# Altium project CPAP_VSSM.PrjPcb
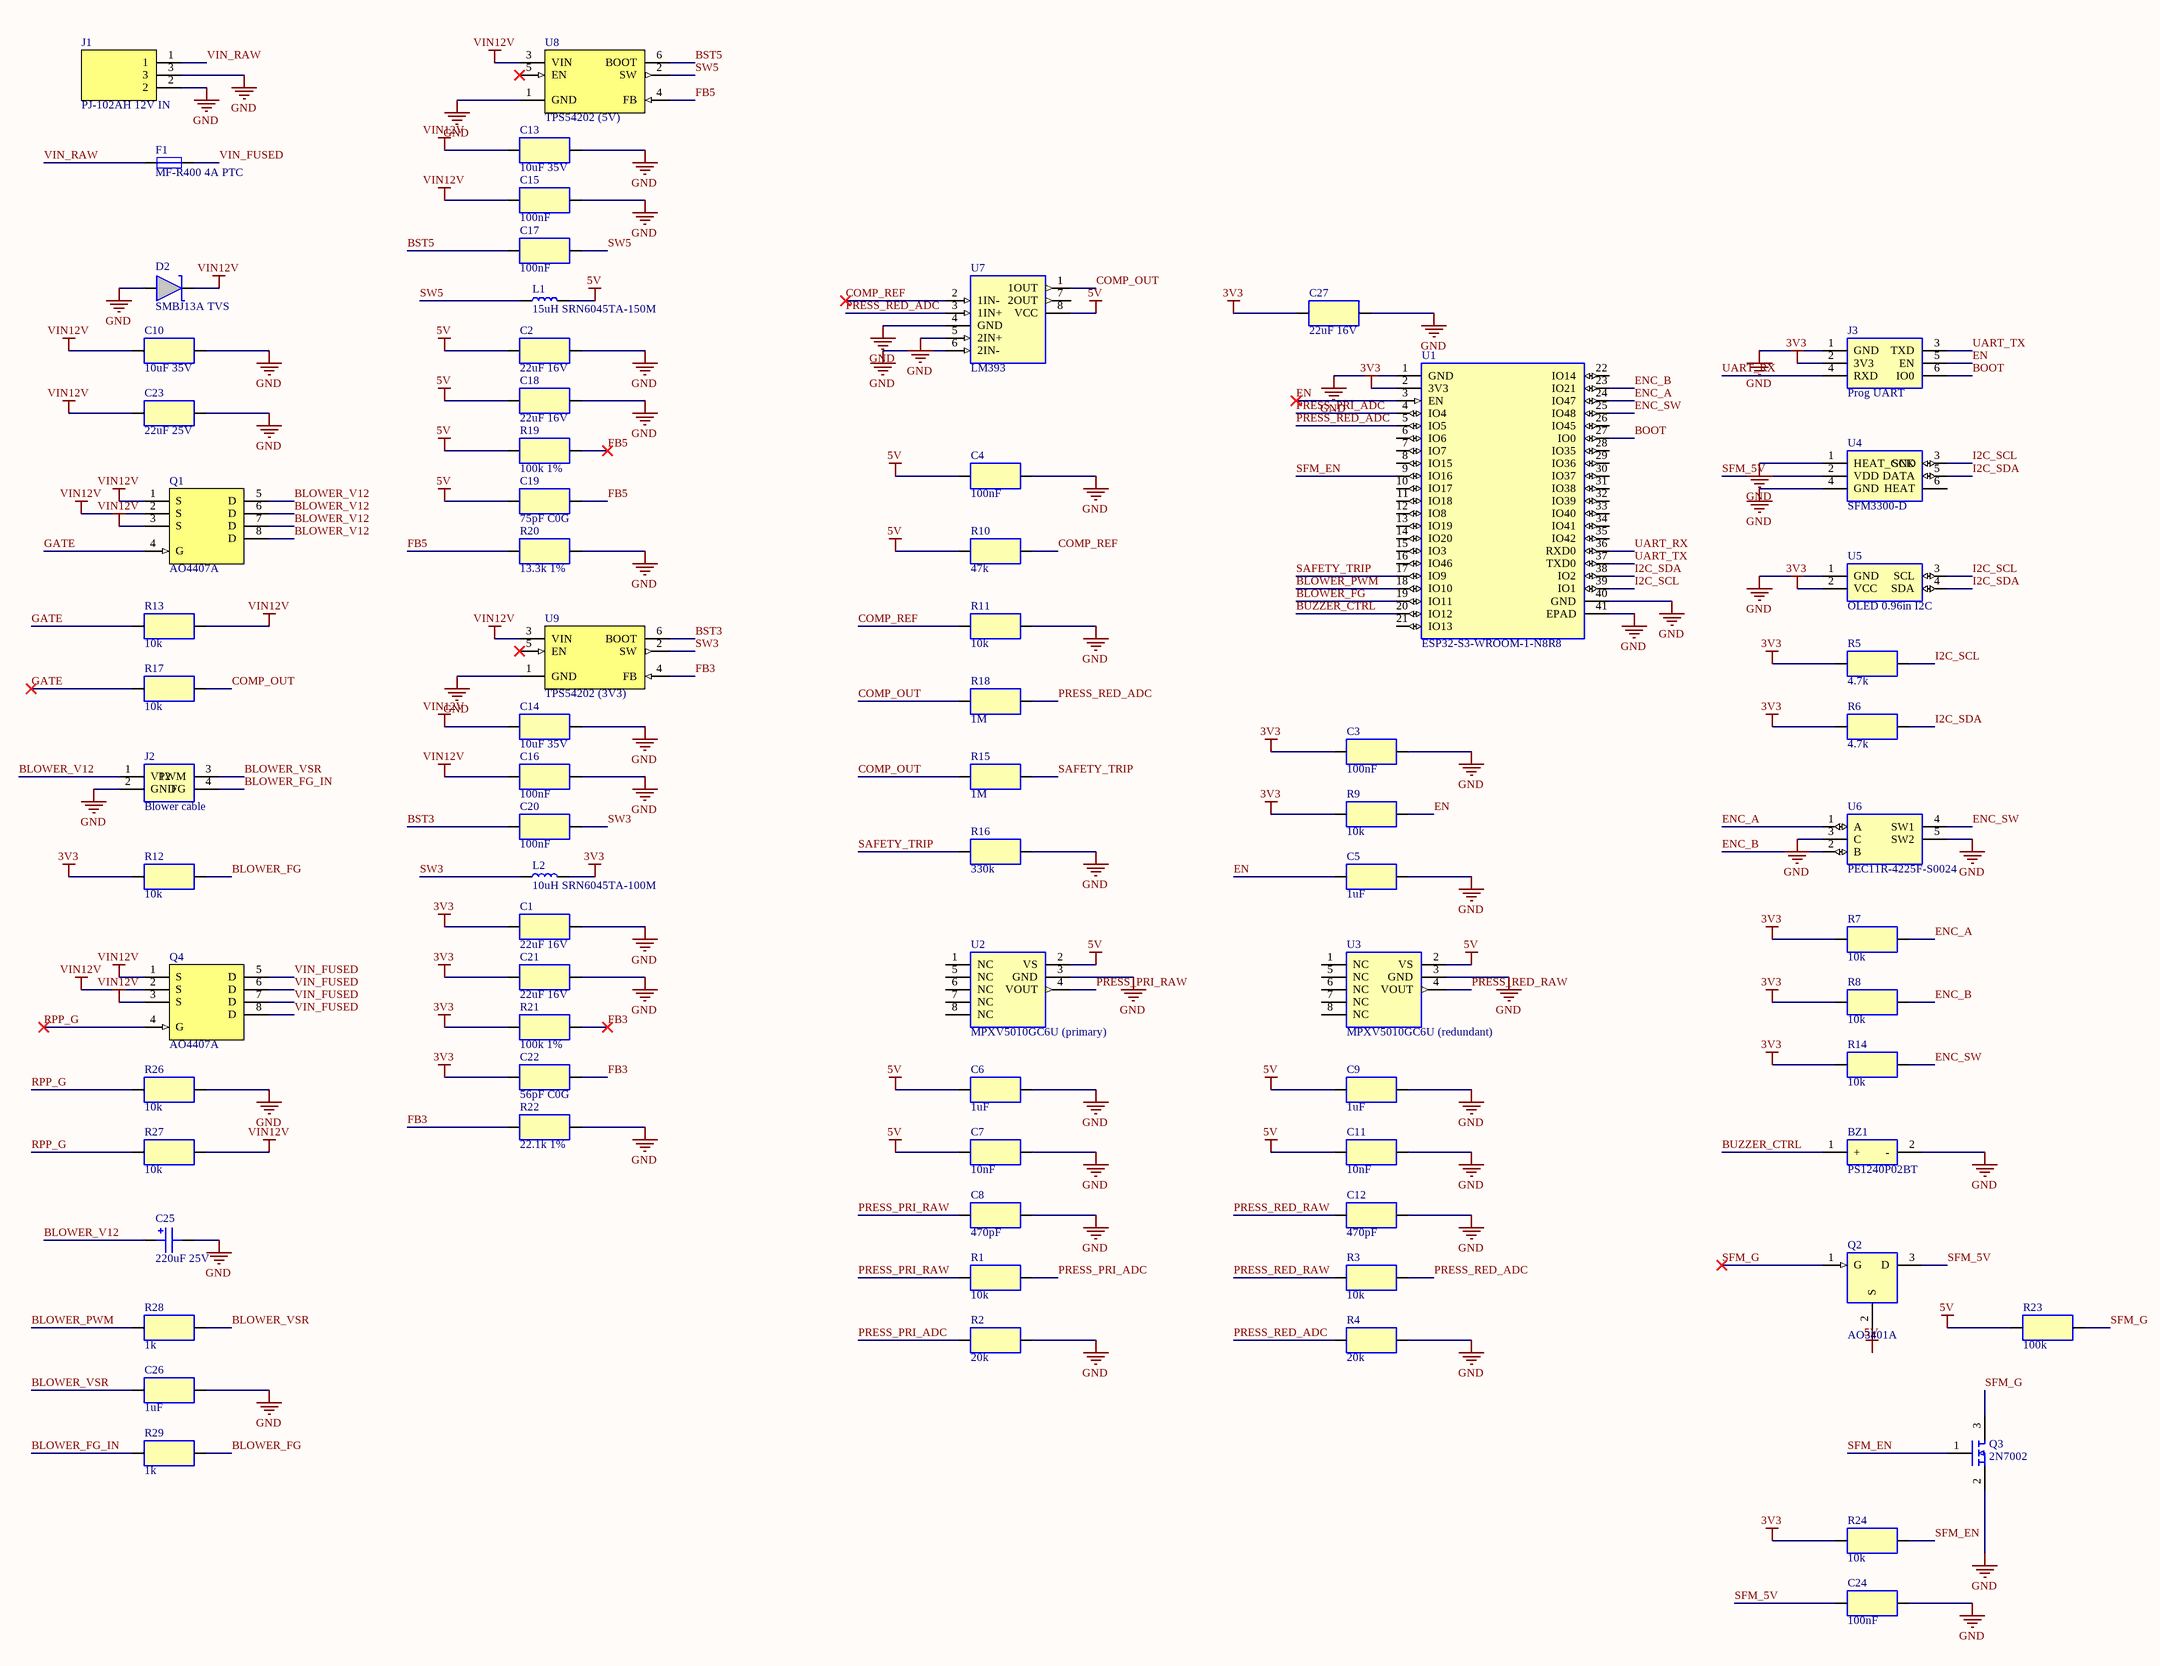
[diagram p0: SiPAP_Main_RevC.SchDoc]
1 sheet, 76 parts. Net scope: global (net labels, ports and power ports of the same name join across sheets).
Board file: SiPAP_PCB.PcbDoc

## Sheet SiPAP_Main_RevC.SchDoc
size 457 x 419 mm; SheetNumber: 1; SheetTotal: 1

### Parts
BZ1  PS1240P02BT  [BUZZER_TDK_PS1240]
C1  22uF 16V  [R_0805]
C2  22uF 16V  [R_0805]
C3  100nF  [R_0805]
C4  100nF  [R_0805]
C5  1uF  [R_0805]
C6  1uF  [R_0805]
C7  10nF  [R_0805]
C8  470pF  [R_0805]
C9  1uF  [R_0805]
C10  10uF 35V  [R_0805]
C11  10nF  [R_0805]
C12  470pF  [R_0805]
C13  10uF 35V  [R_0805]
C14  10uF 35V  [R_0805]
C15  100nF  [R_0805]
C16  100nF  [R_0805]
C17  100nF  [R_0805]
C18  22uF 16V  [R_0805]
C19  75pF C0G  [R_0805]
C20  100nF  [R_0805]
C21  22uF 16V  [R_0805]
C22  56pF C0G  [R_0805]
C23  22uF 25V  [R_0805]
C24  100nF  [R_0805]
C25  220uF 25V  [CAP_RAD_D8_P3.5]
C26  1uF  [R_0805]
C27  22uF 16V  [R_0805]
D2  SMBJ13A TVS  [DIOM_SMB_DO-214AA_BOURNS]
F1  MF-R400 4A PTC  [PTC_RADIAL_MF-R300]
J1  PJ-102AH 12V IN  [CUI_PJ-102AH]
J2  Blower cable  [CONN_HEADER_4_2X2]
J3  Prog UART  [CONN_HEADER_6]
L1  15uH SRN6045TA-150M  [IND_BOURNS_SRN6045TA]
L2  10uH SRN6045TA-100M  [IND_BOURNS_SRN6045TA]
Q1  AO4407A  [SOIC-8]
Q2  AO3401A  [SOT-23]
Q3  2N7002  [SOT-23]
Q4  AO4407A  [SOIC-8]
R1  10k  [R_0805]
R2  20k  [R_0805]
R3  10k  [R_0805]
R4  20k  [R_0805]
R5  4.7k  [R_0805]
R6  4.7k  [R_0805]
R7  10k  [R_0805]
R8  10k  [R_0805]
R9  10k  [R_0805]
R10  47k  [R_0805]
R11  10k  [R_0805]
R12  10k  [R_0805]
R13  10k  [R_0805]
R14  10k  [R_0805]
R15  1M  [R_0805]
R16  330k  [R_0805]
R17  10k  [R_0805]
R18  1M  [R_0805]
R19  100k 1%  [R_0805]
R20  13.3k 1%  [R_0805]
R21  100k 1%  [R_0805]
R22  22.1k 1%  [R_0805]
R23  100k  [R_0805]
R24  10k  [R_0805]
R26  10k  [R_0805]
R27  10k  [R_0805]
R28  1k  [R_0805]
R29  1k  [R_0805]
U1  ESP32-S3-WROOM-1-N8R8  [ESP32-S3-WROOM-1_DS]
U2  MPXV5010GC6U (primary)  [MPXV5010GC6U_482A]
U3  MPXV5010GC6U (redundant)  [MPXV5010GC6U_482A]
U4  SFM3300-D  [CONN_HEADER_6]
U5  OLED 0.96in I2C  [CONN_HEADER_4]
U6  PEC11R-4225F-S0024  [PEC11R-4xxxF-S_DS]
U7  LM393  [SOIC-8]
U8  TPS54202 (5V)  [TI_DDC0006A_SOT23-6]
U9  TPS54202 (3V3)  [TI_DDC0006A_SOT23-6]

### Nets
3V3: C1.1 C3.1 C21.1 C22.1 C27.1 J3.2(3V3) L2.2 R5.1 R6.1 R7.1 R8.1 R9.1 R12.1 R14.1 R21.1 R24.1 U1.2(3V3) U5.2(VCC)
5V: C2.1 C4.1 C6.1 C7.1 C9.1 C11.1 C18.1 C19.1 L1.2 Q2.2(S) R10.1 R19.1 R23.1 U2.2(VS) U3.2(VS) U7.8(VCC)
GND: BZ1.2(-) C1.2 C2.2 C3.2 C4.2 C5.2 C6.2 C7.2 C8.2 C9.2 C10.2 C11.2 C12.2 C13.2 C14.2 C15.2 C16.2 C18.2 C21.2 C23.2 C24.2 C25.2 C26.2 C27.2 D2.2(A) J1.2 J1.3 J2.2(GND) J3.1(GND) Q3.2(S) R2.2 R4.2 R11.2 R16.2 R20.2 R22.2 R26.2 U1.1(GND) U1.40(GND) U1.41(EPAD) U2.3(GND) U3.3(GND) U4.1(HEAT_GND) U4.4(GND) U5.1(GND) U6.3(C) U6.5(SW2) U7.4(GND) U7.5(2IN+) U7.6(2IN-) U8.1(GND) U9.1(GND)
VIN12V: C10.1 C13.1 C14.1 C15.1 C16.1 C23.1 D2.1(K) Q1.1(S) Q1.2(S) Q1.3(S) Q4.1(S) Q4.2(S) Q4.3(S) R13.2 R27.2 U8.3(VIN) U9.3(VIN)
BLOWER_FG: R12.2 R29.2 U1.19(IO11)
BLOWER_FG_IN: J2.4(FG) R29.1
BLOWER_PWM: R28.1 U1.18(IO10)
BLOWER_V12: C25.1 J2.1(V12) Q1.5(D) Q1.6(D) Q1.7(D) Q1.8(D)
BLOWER_VSR: C26.1 J2.3(PWM) R28.2
BOOT: J3.6(IO0) U1.27(IO0)
BST3: C20.1 U9.6(BOOT)
BST5: C17.1 U8.6(BOOT)
BUZZER_CTRL: BZ1.1(+) U1.20(IO12)
COMP_OUT: R15.1 R17.2 R18.1 U7.1(1OUT)
COMP_REF: R10.2 R11.1 U7.2(1IN-)
EN: C5.1 J3.5(EN) R9.2 U1.3(EN)
ENC_A: R7.2 U1.24(IO47) U6.1(A)
ENC_B: R8.2 U1.23(IO21) U6.2(B)
ENC_SW: R14.2 U1.25(IO48) U6.4(SW1)
FB3: C22.2 R21.2 R22.1 U9.4(FB)
FB5: C19.2 R19.2 R20.1 U8.4(FB)
GATE: Q1.4(G) R13.1 R17.1
I2C_SCL: R5.2 U1.39(IO1) U4.3(SCK) U5.3(SCL)
I2C_SDA: R6.2 U1.38(IO2) U4.5(DATA) U5.4(SDA)
PRESS_PRI_ADC: R1.2 R2.1 U1.4(IO4)
PRESS_PRI_RAW: C8.1 R1.1 U2.4(VOUT)
PRESS_RED_ADC: R3.2 R4.1 R18.2 U1.5(IO5) U7.3(1IN+)
PRESS_RED_RAW: C12.1 R3.1 U3.4(VOUT)
RPP_G: Q4.4(G) R26.1 R27.1
SAFETY_TRIP: R15.2 R16.1 U1.17(IO9)
SFM_5V: C24.1 Q2.3(D) U4.2(VDD)
SFM_EN: Q3.1(G) R24.2 U1.9(IO16)
SFM_G: Q2.1(G) Q3.3(D) R23.2
SW3: C20.2 L2.1 U9.2(SW)
SW5: C17.2 L1.1 U8.2(SW)
UART_RX: J3.4(RXD) U1.36(RXD0)
UART_TX: J3.3(TXD) U1.37(TXD0)
VIN_FUSED: F1.2 Q4.5(D) Q4.6(D) Q4.7(D) Q4.8(D)
VIN_RAW: F1.1 J1.1

Not connected (* = marked no-connect by the designer): U1 6(IO6) 7(IO7) 8(IO15) 10(IO17) 11(IO18) 12(IO8) 13(IO19) 14(IO20) 15(IO3) 16(IO46) 21(IO13) 22(IO14) 26(IO45) 28(IO35) 29(IO36) 30(IO37) 31(IO38) 32(IO39) 33(IO40) 34(IO41) 35(IO42); U2 1(NC) 5(NC) 6(NC) 7(NC) 8(NC); U3 1(NC) 5(NC) 6(NC) 7(NC) 8(NC); U4 6(HEAT); U7 7(2OUT); U8 5(EN)*; U9 5(EN)*

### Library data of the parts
BZ1 = BUZZER: Generic piezo buzzer, 2-pin; Manufacturer: TDK
C1 C2 C18 C21 = CAPACITOR: Generic capacitor, 2-pin; Manufacturer: Murata; Manufacturer Part Number: GRM21BR61C226ME44
C3 C4 C15-C17 C20 C24 = CAPACITOR: Generic capacitor, 2-pin; Manufacturer: Samsung; Manufacturer Part Number: CL21B104KBCNNNC
C5 C6 C9 C26 = CAPACITOR: Generic capacitor, 2-pin; Manufacturer: Samsung; Manufacturer Part Number: CL21B105KAFNNNE
C7 C11 = CAPACITOR: Generic capacitor, 2-pin; Manufacturer: Samsung; Manufacturer Part Number: CL21B103KBANNNC
C8 C12 = CAPACITOR: Generic capacitor, 2-pin; Manufacturer: Samsung; Manufacturer Part Number: CL21C471JBANNNC
C10 C13 C14 = CAPACITOR: Generic capacitor, 2-pin; Manufacturer: Murata; Manufacturer Part Number: GRM21BR6YA106KE43
C19 = CAPACITOR: Generic capacitor, 2-pin; Manufacturer: Murata; Manufacturer Part Number: GRM2165C1H750JA01
C22 = CAPACITOR: Generic capacitor, 2-pin; Manufacturer: Murata; Manufacturer Part Number: GRM2165C1H560JA01
C23 = CAPACITOR: Generic capacitor, 2-pin; Manufacturer: Murata; Manufacturer Part Number: GRM21BR61E226ME44
C25 = CAP_POL: Polarized capacitor (aluminium electrolytic), pin 1 = +; Manufacturer: Panasonic; Manufacturer Part Number: EEU-FC1E221
C27 = CAPACITOR: MLCC 22uF X5R 16V 0805 - U1 3V3 bulk (Espressif WROOM-1 DS v1.8 Fig 9-1 C1); Manufacturer: Murata; Manufacturer Part Number: GRM21BR61C226ME44
D2 = TVS_UNI: Unidirectional TVS (Bourns SMBJ13A, VRWM 13V, Vc 21.5V@10/1000us, 28.0V@8/20us), pin1 = cathode
F1 = FUSE_PTC: Resettable PTC fuse (Bourns MF-R300)
J1 = CONN_DCJACK3: DC power jack 3-pin (Same Sky PJ-102AH): 1 centre pin (+), 2 sleeve, 3 switch
J2 = CONN_BLOWER4: 4-pin blower cable connector: 12V, GND, PWM, FG; Manufacturer: Wurth Elektronik; Manufacturer Part Number: 61300421121
J3 = CONN_UART6: 6-pin 2.54mm programming header (USB-UART): GND 3V3 TXD RXD EN IO0; Manufacturer: Wurth Elektronik; Manufacturer Part Number: 61300611121
L1 L2 = INDUCTOR: Power inductor (Bourns SRN6045TA)
Q1 Q4 = AO4407A: AOS AO4407A P-channel MOSFET -30V -12A, SOIC-8 (S=1,2,3 G=4 D=5-8, datasheet Rev 11.1 p1 top view); Manufacturer: Alpha & Omega Semiconductor
Q2 = AO3401A: Alpha&Omega AO3401A P-channel MOSFET, SOT-23 (AOS datasheet); Manufacturer: Alpha & Omega Semiconductor
Q3 = 2N7002: N-channel MOSFET 60V 0.2A SOT-23 (Diodes 2N7002 DS11303 p1: 1=G 2=S 3=D); Manufacturer: Diodes Incorporated; Manufacturer Part Number: 2N7002-7-F
R1 R3 R7-R9 R11-R14 R17 R24 R26 R27 = RESISTOR: Generic resistor, 2-pin; Manufacturer: Yageo; Manufacturer Part Number: RC0805FR-0710KL
R2 R4 = RESISTOR: Generic resistor, 2-pin; Manufacturer: Yageo; Manufacturer Part Number: RC0805FR-0720KL
R5 R6 = RESISTOR: Generic resistor, 2-pin; Manufacturer: Yageo; Manufacturer Part Number: RC0805FR-074K7L
R10 = RESISTOR: Generic resistor, 2-pin; Manufacturer: Yageo; Manufacturer Part Number: RC0805FR-0747KL
R15 R18 = RESISTOR: Generic resistor, 2-pin; Manufacturer: Yageo; Manufacturer Part Number: RC0805FR-071ML
R16 = RESISTOR: Generic resistor, 2-pin; Manufacturer: Yageo; Manufacturer Part Number: RC0805FR-07330KL
R19 R21 R23 = RESISTOR: Generic resistor, 2-pin; Manufacturer: Yageo; Manufacturer Part Number: RC0805FR-07100KL
R20 = RESISTOR: Generic resistor, 2-pin; Manufacturer: Yageo; Manufacturer Part Number: RC0805FR-0713K3L
R22 = RESISTOR: Generic resistor, 2-pin; Manufacturer: Yageo; Manufacturer Part Number: RC0805FR-0722K1L
R28 R29 = RESISTOR: Generic resistor, 2-pin; Manufacturer: Yageo; Manufacturer Part Number: RC0805FR-071KL
U1 = ESP32-S3-WROOM-1: Espressif ESP32-S3-WROOM-1 WiFi+BLE module, 41 pins (datasheet v1.8)
U2 U3 = MPXV5010GC6U: NXP/Motorola MPXV5010GC6U pressure sensor, SOP-8 (Case 482A), 0-10kPa analog output; Manufacturer: NXP
U4 = SFM3300-D: Sensirion SFM3300-D digital flow meter, I2C addr 0x40, 6-pad connector (Datasheet D1 v1.4); Manufacturer: Wurth Elektronik; Manufacturer Part Number: 61300611121
U5 = SSD1306_OLED_I2C: 0.96in 128x64 I2C OLED module, 4-pin (GND,VCC,SCL,SDA), addr 0x3C; Manufacturer: Wurth Elektronik; Manufacturer Part Number: 61300411121
U6 = PEC11R-4220F-S0024: Bourns PEC11R rotary encoder w/ push switch, 5 terminals (Bourns datasheet Rev 04/26)
U7 = LM393: Dual comparator, DIP-8/SOIC-8 (TI datasheet SLCS006); Manufacturer: Texas Instruments; Manufacturer Part Number: LM393DR
U8 U9 = TPS54202: TI TPS54202 4.5-28V 2A synchronous buck, SOT-23-6 (DDC); Manufacturer: Texas Instruments; Manufacturer Part Number: TPS54202DDCR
